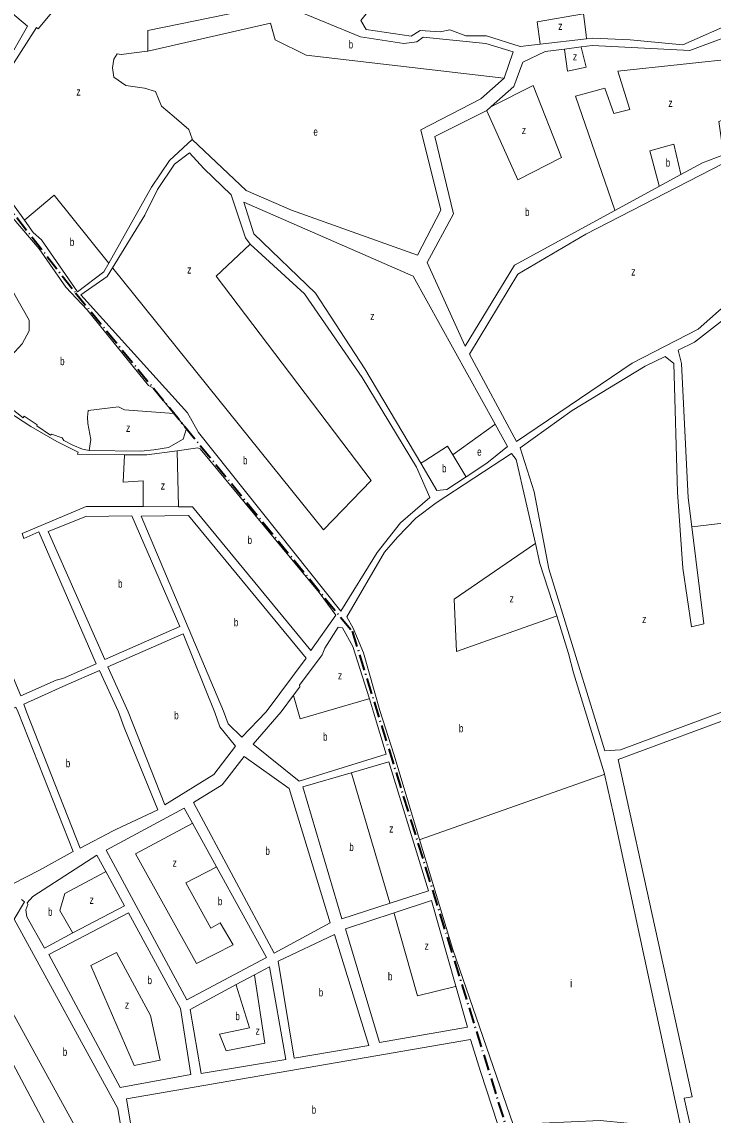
# Model space of a CAD drawing. Extents: x 639657 to 671642, y 222838 to 252123.
# Drawn here: x 644419 to 645283, y 235497 to 236863 of the extents above; entities that cross this region are included whole.
import ezdxf

# ---------------------------------------------------------------- set-up
doc = ezdxf.new("R2010")
doc.units = 0
doc.header["$LTSCALE"] = 4
doc.linetypes.add('DOT_DASHED', pattern=[7.7, 5, -1.2, 0.3, -1.2])
for name, color, linetype, lineweight in [('1', 7, 'Continuous', 13), ('21', 7, 'Continuous', 13), ('4', 7, 'DOT_DASHED', 40)]:
    doc.layers.add(name, color=color, linetype=linetype, lineweight=lineweight)
doc.layers.add('7', color=7, linetype='Continuous')

msp = doc.modelspace()

# ---------------------------------------------------------------- linework, layer by layer
at = {"layer": '1'}
for p, q in [((644699.34, 236652.34), (644632.16, 236716.06)), ((644743.067, 236000.776), (644758.617, 236021.409)), ((644770.275, 235906.854), (644830.966, 235924.586)), ((644536.536, 235853.682), (644533.089, 235851.881)), ((644512.839, 235821.325), (644523.931, 235801.017)), ((644931.427, 235764.669), (644884.557, 235749.275))]:
    msp.add_line(p, q, dxfattribs=at)
for points in [[(644981.51, 236891.13), (645027.8, 236902.35), (645063.22, 236914.68), (645167.09, 236964.55), (645213.41, 236999.46), (645273.08, 237026.45), (645276.75, 237017.65), (645297.14, 237026.51), (645314.33, 237024.18), (645333.93, 237006.61), (645413.63, 236923.23), (645353.8, 236878.62), (645313.44, 236864.14), (645245.41, 236834.33), (645179.43, 236840.62), (645133.02, 236842.45), (645125.138, 236841.542), (645067.178, 236834.862)], [(644422.317, 236615.024), (644366.95, 236691.57), (644340.18, 236720.48), (644338.87, 236725.63), (644381.39, 236790.26), (644395.76, 236798.7), (644405.83, 236806.26), (644437.23, 236856.02), (644439.6, 236854.09), (644492.65, 236918.55), (644503.31, 236943.09), (644536.32, 236964.06), (644544.04, 236970.1), (644608.04, 236982.17), (644615.57, 236980.69), (644617.449, 236978.338), (644647.537, 236940.675)], [(644697.071, 236906.469), (644753.32, 236880.86), (644842.66, 236844.23), (644896.65, 236836.06), (644912.76, 236837.84), (644920.69, 236843.88), (644999.18, 236836.02), (645033.35, 236825.63), (645022.22, 236792.67)], [(645067.178, 236834.862), (645042, 236831.96), (645000, 236845.26), (644974.21, 236845.59), (644954.19, 236852.82), (644942.16, 236850.63), (644917, 236852.25), (644905.86, 236844.9), (644849.72, 236853.5), (644843.01, 236864.65), (644868.04, 236896.33), (644876.4, 236900.45), (644966.08, 236890.47), (644981.51, 236891.13)], [(645118.258, 236831.612), (645132.61, 236833.42), (645254.02, 236827.26), (645295.45, 236842.61), (645352.3, 236869.17)], [(645005.914, 236757.058), (645034.38, 236782.26), (645045.49, 236812.68), (645073.54, 236825.98), (645097.398, 236828.985), (645118.258, 236831.612)], [(645022.22, 236792.67), (644992.95, 236766.83), (644918.09, 236727.87), (644943.07, 236627.75), (644913.8, 236571.19), (644756.32, 236627.75), (644699.34, 236652.34)], [(645160.545, 236627.173), (645035.18, 236558.79), (644973.29, 236457.73), (644925.88, 236562.17), (644958.57, 236623.13), (644935.32, 236719.63), (645000.28, 236752.07), (645005.914, 236757.058)], [(644305.662, 236676.641), (644309.259, 236678.101), (644316.571, 236685.53), (644335.428, 236713.445), (644407.109, 236618.838), (644440.59, 236579.448), (644473.86, 236531.205), (644500.893, 236502.988), (644577.297, 236408.545), (644583.271, 236404.953), (644609.033, 236373.678)], [(644632.16, 236716.06), (644603.82, 236689.46), (644581.17, 236656.49), (644527.837, 236561.405)], [(644532.53, 236555.578), (644572.93, 236621.22), (644588.7, 236653.56), (644609.86, 236684.97), (644628.6, 236699.37), (644646.41, 236679.72), (644680.91, 236646.95), (644698.78, 236592.9), (644704.4, 236584.97)], [(645296.368, 236696.643), (645270.06, 236686.91), (645242.966, 236672.131), (645216.113, 236657.484), (645160.545, 236627.173)], [(644917.72, 236311.218), (644847.95, 236429.5), (644786.32, 236524.03), (644709.08, 236598.1), (644696.53, 236637.39), (644908.41, 236545.21), (645010.827, 236360.041), (645026.27, 236332.12)], [(644527.837, 236561.405), (644521.62, 236550.32), (644488.51, 236525.5), (644443.43, 236590.64), (644433.3, 236599.84), (644422.317, 236615.024)], [(644704.4, 236584.97), (644772.57, 236523.12), (644844.34, 236418.31), (644912.49, 236306.39), (644928.98, 236268.41), (644892.56, 236236.69), (644863.26, 236199.83), (644817.76, 236126.37)], [(644817.76, 236126.37), (644639.77, 236349.84), (644626.34, 236374.5), (644492.93, 236521.63), (644525.73, 236544.53), (644532.53, 236555.578)], [(645256.765, 236231.779), (645252.27, 236267.98), (645243.78, 236436.14), (645239.7, 236452.44), (645260.08, 236462.5), (645342.43, 236526.92), (645361.64, 236493.77), (645382.64, 236388.25), (645428.896, 236252.387), (645440.072, 236219.56)], [(644503.381, 236327.362), (644494.752, 236328.981), (644482.804, 236333.785), (644471.582, 236339.798), (644469.588, 236343.271), (644456.312, 236347.683), (644455.077, 236346.479), (644437.714, 236357.941), (644438.138, 236359.357), (644421.985, 236369.993), (644420.538, 236368.081), (644390.698, 236391.254), (644383.702, 236393.261), (644348.483, 236417.612), (644336.421, 236429.927), (644311.232, 236467.766), (644282.235, 236492.46), (644279.645, 236489.538)], [(644279.645, 236489.538), (644300.847, 236467.172), (644302.999, 236468.467), (644314.954, 236455.645), (644314.116, 236453.625), (644336.632, 236422.008), (644346.71, 236413.977), (644375.67, 236393.758), (644378.15, 236388.452), (644364.587, 236360.183), (644366.324, 236343.721), (644369.182, 236344.501), (644369.052, 236359.22), (644383.7, 236384.532), (644388.229, 236380.421), (644390.398, 236383.138), (644430.175, 236357.112), (644462.815, 236338.374), (644489.415, 236325.083), (644488.468, 236322.454), (644547.422, 236321.999)], [(645135.49, 235992.58), (645077.94, 236179.36), (645059.44, 236275.56), (645042.11, 236330.73), (645107.19, 236377.37), (645198.49, 236432.71), (645223.5, 236444.66), (645234.12, 236435.84), (645238.88, 236275.37), (645245.37, 236180.25), (645256.18, 236107.08), (645271.83, 236110.45), (645256.765, 236231.779)], [(644503.381, 236327.362), (644567.672, 236326.437), (644584.171, 236327.875), (644602.521, 236330.917), (644620.705, 236341.593), (644624.75, 236354.699), (644609.033, 236373.678)], [(644547.422, 236321.999), (644575.145, 236321.785), (644613.041, 236327)], [(644613.041, 236327), (644639.247, 236330.606), (644641.98, 236329.459), (644790.903, 236149.633), (644811.518, 236121.263), (644780.502, 236077.193), (644632.468, 236256.89), (644614.749, 236256.941), (644570.55, 236257.066)], [(645026.27, 236332.12), (645000.45, 236311.4), (644974.406, 236294.393)], [(644936.96, 236261.95), (645031.17, 236323.62), (645037.21, 236315.9), (645061.059, 236211.027)], [(644974.406, 236294.393), (644950.22, 236278.6), (644937.75, 236277.26), (644917.72, 236311.218)], [(644470.28, 236042.411), (644461.955, 236040.072), (644417.825, 236020.467), (644349.251, 236182.93), (644358.912, 236191.145), (644354.595, 236195.964), (644320.286, 236168.538), (644324.505, 236164.024), (644340.922, 236175.614), (644407.789, 236014.997), (644372.509, 236000.066), (644335.879, 236076.706), (644310.934, 236143.572), (644289.704, 236180.655), (644245.021, 236221.961), (644241.847, 236228.797), (644244.314, 236239.427), (644254.24, 236252.816), (644254.208, 236275.756), (644250.453, 236281.83), (644249.217, 236283.83)], [(644916.403, 235841.076), (644884.27, 235947.54), (644866.74, 236002.18), (644846.13, 236074.48), (644833.11, 236105.37), (644825.53, 236119.31), (644872.28, 236200.29), (644888.76, 236219.05), (644911.45, 236242.77), (644936.96, 236261.95)], [(644570.55, 236257.066), (644499.494, 236257.267), (644419.325, 236223.454), (644421.488, 236217.137), (644440.311, 236225.655), (644512.109, 236060.516), (644470.28, 236042.411)], [(645061.059, 236211.027), (645066.75, 236186), (645087.745, 236120.435)], [(645087.745, 236120.435), (645102.7, 236073.73), (645108.77, 236049.25), (645147.47, 235923.25), (645147.628, 235922.555)], [(644758.617, 236021.409), (644766.43, 236031.776), (644766.354, 236034.01), (644794.482, 236072.062), (644798.036, 236080.041), (644814.581, 236106.604), (644820.065, 236105.441), (644832.832, 236082.163), (644853.583, 236016.954)], [(644473.946, 236034.148), (644515.978, 236052.251), (644539.886, 236000.825), (644546.803, 235981.135), (644589.205, 235878.101), (644536.536, 235853.682)], [(644533.089, 235851.881), (644491.788, 235830.3), (644424.912, 236000.493), (644421.671, 236010.273), (644473.946, 236034.148)], [(644853.583, 236016.954), (644858.864, 236000.361), (644874.514, 235947.771), (644765.789, 235913.949), (644708.18, 235960.182), (644743.067, 236000.776)], [(645346.911, 236025.077), (645309.94, 236012.82), (645309.79, 236005.89), (645167.7, 235953.03), (645148.15, 235951.84), (645135.49, 235992.58)], [(644398.968, 236000.48), (644411.553, 236006.429), (644414.533, 236000.406), (644483.163, 235826.112), (644441.158, 235802.942)], [(644361.55, 235959.985), (644307.372, 235929.063), (644332.056, 235886.694), (644331.656, 235883.85), (644345.732, 235859.827), (644348.009, 235841.964), (644346.333, 235820.13), (644374.898, 235769.04), (644441.158, 235802.942)], [(644830.966, 235924.586), (644877.686, 235938.236), (644927.64, 235776.842), (644879.459, 235761.33)], [(645147.628, 235922.555), (645158.96, 235872.6), (645243.5, 235479.86), (645142.2, 235489.99), (645033.27, 235485.03), (644957.87, 235703.69), (644916.403, 235841.076)], [(644879.459, 235761.33), (644819.12, 235741.904), (644770.275, 235906.854)], [(644524.304, 235827.755), (644622.013, 235880.329), (644632.418, 235861.474), (644662.536, 235806.898)], [(644482.75, 235724.293), (644447.176, 235705.488), (644425.447, 235744.312), (644424.004, 235753.242), (644426.629, 235759.951), (644425.507, 235762.08), (644432.702, 235769.716), (644512.839, 235821.325)], [(644662.536, 235806.898), (644725.057, 235693.605), (644625.317, 235640.619), (644524.304, 235827.755)], [(644523.931, 235801.017), (644547.222, 235758.373), (644482.75, 235724.293)], [(644409.604, 235741.727), (644422.253, 235763.391), (644418.792, 235766.325)], [(644884.557, 235749.275), (644823.822, 235729.327), (644866.416, 235587.508), (644976.07, 235606.627), (644961.671, 235657.601), (644931.427, 235764.669)], [(644382.441, 235671.184), (644384.706, 235658.296), (644402.848, 235633.27), (644520.789, 235418.871), (644520.29, 235415.113), (644528.453, 235399.602), (644555.57, 235403.032), (644539.078, 235504.821), (644409.604, 235741.727)]]:
    msp.add_lwpolyline(points, dxfattribs=at)
for points in [[(644331.34, 236726.68), (644334.35, 236727.98), (644357.4, 236768.03), (644376.65, 236793.68), (644388.64, 236805.33), (644398.94, 236809.88), (644425.91, 236857.51), (644329.66, 236938.9), (644272.52, 236945.57), (644232.47, 236992.44), (644223.34, 236970.39), (644193.11, 236949.43), (644188, 236937.16), (644186.563, 236911.315)], [(645366.48, 236708.85), (645380.96, 236581.58), (645264.77, 236478.84), (645182.15, 236436.32), (645037.57, 236338.69), (644978.64, 236447.6), (645038.99, 236547.45), (645124.26, 236597.46), (645295.12, 236685.66)], [(644522.859, 236066.181), (644451.812, 236226.033), (644499.041, 236244.788), (644556.637, 236245.562), (644616.749, 236107.351)], [(644671.174, 236001.502), (644568.131, 236245.331), (644627.456, 236246.086), (644774.694, 236067.92), (644724.548, 236000.68), (644693.936, 235969.075), (644677.033, 235985.779)], [(644552.091, 236000.485), (644526.714, 236056.698), (644620.609, 236098.274), (644660.512, 235999.841), (644666.578, 235981.789), (644686.038, 235957.883), (644658.895, 235922.369), (644598.028, 235884.422)], [(645326.87, 236001.17), (645164.55, 235940.98), (645257.22, 235519.48), (645247.34, 235517.92), (645256.64, 235474.78), (645294.7, 235471.78), (645365.62, 235472.21), (645420.92, 235462.45), (645423.14, 235485.24), (645412.03, 235578.44), (645399.43, 235739.54), (645380.89, 235852.03)], [(644633.578, 235887.368), (644669.491, 235909.302), (644697.142, 235944.92), (644753.212, 235904.977), (644804.502, 235736.886), (644734.493, 235698.912)], [(644452.885, 235697.28), (644552.322, 235749.656), (644617.519, 235629.834), (644630.31, 235547.223), (644542.064, 235531.33)], [(644809.819, 235722.281), (644852.71, 235583.508), (644759.385, 235567.702), (644739.596, 235688.875)], [(644728.741, 235682.142), (644748.924, 235566.25), (644643.209, 235548.58), (644629.306, 235628.853), (644686.858, 235659.696), (644709.817, 235672)], [(644263.41, 235569.406), (644371.876, 235627.697), (644475.649, 235433.157), (644343.505, 235421.502)], [(644993.1, 235549.753), (644980.043, 235591.087), (644549.716, 235517.138), (644568.364, 235405.81), (644971.73, 235472.676), (644998.433, 235479.353), (645013.955, 235486.352)]]:
    msp.add_lwpolyline(points, close=True, dxfattribs=at)
at = {"layer": '21'}
for points in [[(644697.071, 236906.469), (644697.037, 236905.969), (644694.98, 236876.139), (644576.393, 236852.078), (644576.393, 236826.358)], [(645067.178, 236834.862), (645067.107, 236835.362), (645063.18, 236862.864), (645121.23, 236872.82), (645124.513, 236846.542), (645125.138, 236841.542)], [(644576.393, 236826.358), (644729.81, 236861.205), (644735.615, 236840.463), (644774.591, 236821.38), (645021.72, 236792.728), (645022.22, 236792.67)], [(645097.398, 236828.985), (645097.469, 236828.485), (645101.327, 236801.469), (645124.547, 236806.447), (645118.383, 236831.112), (645118.258, 236831.612)], [(644576.393, 236826.358), (644575.893, 236826.295), (644543.222, 236822.21), (644538.246, 236823.04), (644534.1, 236816.402), (644532.441, 236805.617), (644534.1, 236794.001), (644549.027, 236783.216), (644572.247, 236779.897), (644586.345, 236775.749), (644593.808, 236757.496), (644609.564, 236744.221), (644627.809, 236728.458), (644631.985, 236716.56), (644632.16, 236716.06)], [(645111.279, 236769.941), (645147.767, 236779.897), (645159.377, 236748.37), (645179.28, 236753.348), (645164.353, 236801.469), (645320.257, 236818.062), (645326.891, 236751.689), (645290.403, 236738.414), (645296.297, 236697.143), (645296.368, 236696.643)], [(645000.28, 236752.07), (645000.504, 236751.57), (645039.132, 236665.403), (645093.864, 236693.612), (645058.205, 236783.216), (645006.414, 236757.308), (645005.914, 236757.058)], [(645111.279, 236769.941), (645160.372, 236627.673), (645160.545, 236627.173)], [(645216.113, 236657.484), (645215.978, 236657.984), (645204.158, 236701.908), (645234.012, 236710.205), (645242.848, 236672.631), (645242.966, 236672.131)], [(644527.837, 236561.405), (644527.434, 236561.905), (644459.465, 236646.321), (644422.817, 236615.445), (644422.317, 236615.024)], [(644320.521, 236636.702), (644325.072, 236629.873), (644347.154, 236601.89), (644375.125, 236568.015), (644408.984, 236523.831), (644428.121, 236489.956), (644428.121, 236476.701), (644419.289, 236460.5), (644400.917, 236440.588)], [(644704.4, 236584.97), (644703.9, 236584.502), (644661.809, 236545.101), (644855.861, 236289.563), (644796.152, 236228.168), (644532.933, 236555.078), (644532.53, 236555.578)], [(644609.033, 236373.678), (644547.529, 236377.921), (644539.945, 236381.864), (644502.041, 236377.214), (644501.028, 236369.004), (644501.441, 236360.981), (644505.171, 236340.943), (644503.381, 236327.362)], [(644957.799, 236321.844), (644958.299, 236322.204), (645010.327, 236359.681), (645010.827, 236360.041)], [(644614.749, 236256.941), (644614.737, 236257.44), (644613.053, 236326.5), (644613.041, 236327)], [(644917.72, 236311.218), (644922.72, 236314.425), (644951.227, 236332.707), (644957.799, 236321.844)], [(644570.55, 236257.066), (644570.55, 236257.566), (644570.55, 236289.286), (644545.524, 236287.813), (644547.394, 236321.499), (644547.422, 236321.999)], [(644957.799, 236321.844), (644974.104, 236294.893), (644974.406, 236294.393)], [(645428.896, 236252.387), (645428.396, 236252.327), (645257.265, 236231.839), (645256.765, 236231.779)], [(645061.059, 236211.027), (645060.559, 236210.684), (644959.643, 236141.362), (644962.359, 236076.159), (645087.245, 236120.258), (645087.745, 236120.435)], [(644758.617, 236021.409), (644758.76, 236020.91), (644767.08, 235991.778), (644853.083, 236016.808), (644853.583, 236016.954)], [(644830.966, 235924.586), (644831.115, 235924.086), (644879.31, 235761.83), (644879.459, 235761.33)], [(645147.628, 235922.555), (645147.128, 235922.379), (644916.903, 235841.252), (644916.403, 235841.076)], [(644632.418, 235861.474), (644631.918, 235861.205), (644560.948, 235823.032), (644637.499, 235686.061), (644683.135, 235709.626), (644666.942, 235736.873), (644655.165, 235730.245), (644624.25, 235786.948), (644662.036, 235806.637), (644662.536, 235806.898)], [(644482.75, 235724.293), (644482.464, 235724.793), (644466.732, 235752.338), (644472.62, 235773.693), (644523.431, 235800.751), (644523.931, 235801.017)], [(644884.557, 235749.275), (644884.697, 235748.775), (644913.524, 235645.558), (644961.171, 235657.476), (644961.671, 235657.601)], [(644709.817, 235672), (644709.894, 235671.5), (644722.883, 235586.646), (644674.302, 235577.073), (644666.206, 235597.692), (644703.745, 235605.792), (644687.015, 235659.196), (644686.858, 235659.696)]]:
    msp.add_lwpolyline(points, dxfattribs=at)
msp.add_lwpolyline([(644505.118, 235683.513), (644537.394, 235700.053), (644580.086, 235621.257), (644591.863, 235565.29), (644559.476, 235558.663)], close=True, dxfattribs=at)
at = {"layer": '4'}
for points in [[(644184.36, 236911.02), (644336.866, 236715.574), (644486.077, 236524.352)], [(644486.077, 236524.352), (644832.049, 236101.279), (645111.539, 235201.409), (645049.402, 234891.773), (645039.509, 234842.474), (645039.503, 234842.444), (645027.741, 234783.832)]]:
    msp.add_lwpolyline(points, dxfattribs=at)

# ---------------------------------------------------------------- texts
at = {"layer": '7'}
for s, width, p in [('z', 0.8, (645089.717, 236852.908)), ('b', 0.75, (644827.665, 236829.677)), ('z', 0.8, (645107.962, 236814.743)), ('z', 0.8, (644487.239, 236770.763)), ('z', 0.8, (645227.378, 236756.667)), ('e', 0.75, (644783.607, 236720.697)), ('z', 0.8, (645044.107, 236722.65)), ('b', 0.75, (645224.061, 236681.996)), ('b', 0.75, (645048.147, 236620.307)), ('b', 0.75, (644479.014, 236582.841)), ('z', 0.8, (644625.729, 236548.412)), ('z', 0.8, (645180.938, 236545.931)), ('z', 0.8, (644854.61, 236490.335)), ('b', 0.75, (644466.881, 236433.894)), ('z', 0.8, (644549.293, 236350.549)), ('e', 0.75, (644988.287, 236320.776)), ('b', 0.75, (644695.551, 236309.991)), ('b', 0.75, (644944.335, 236300.035)), ('z', 0.8, (644592.721, 236278.382)), ('b', 0.75, (644701.256, 236210.366)), ('b', 0.75, (644539.321, 236155.871)), ('z', 0.8, (645028.887, 236137.287)), ('b', 0.75, (644684.132, 236107.58)), ('z', 0.8, (645194.527, 236111.478)), ('z', 0.8, (644814.276, 236041.258)), ('b', 0.75, (644609.537, 235991.348)), ('b', 0.75, (644965.482, 235975.093)), ('b', 0.75, (644795.607, 235964.619)), ('b', 0.75, (644473.977, 235931.43)), ('z', 0.8, (644878.314, 235849.793)), ('b', 0.75, (644828.451, 235826.815)), ('b', 0.75, (644723.592, 235821.916)), ('z', 0.8, (644607.442, 235807.081)), ('z', 0.8, (644503.656, 235760.688)), ('b', 0.75, (644664.135, 235759.001)), ('b', 0.75, (644451.756, 235745.732)), ('z', 0.8, (644922.478, 235703.248)), ('b', 0.75, (644576.151, 235660.309)), ('b', 0.75, (644876.784, 235665.042)), ('b', 0.75, (644790.235, 235644.991)), ('z', 0.8, (644547.82, 235629.608)), ('b', 0.75, (644686.007, 235615.361)), ('z', 0.8, (644711.227, 235597.205)), ('b', 0.75, (644470.191, 235570.664)), ('b', 0.75, (644781.411, 235498.448))]:
    msp.add_text(s, height=10, dxfattribs=dict(at, width=width)).set_placement(p)
msp.add_text('i', height=10, dxfattribs=at).set_placement((645104.24, 235656.415))

doc.saveas('drawing.dxf')
